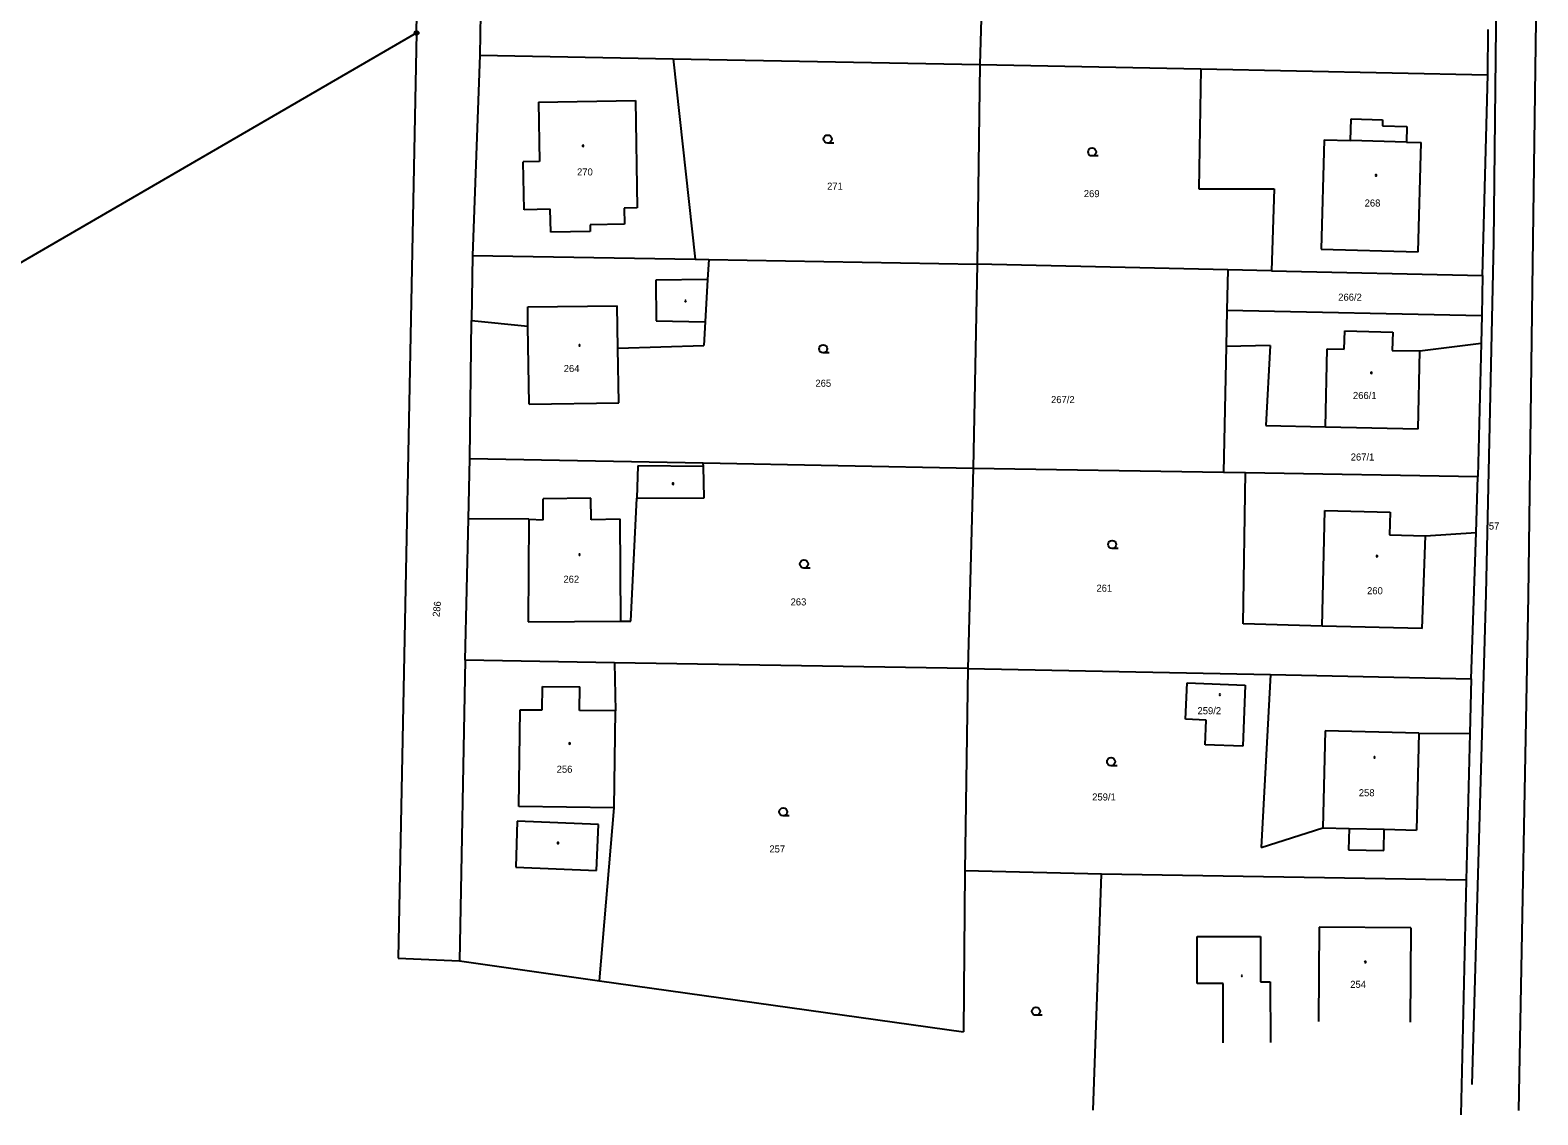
# Model space of a CAD drawing. Extents: x -454285 to -453563, y -1108687 to -1108249.
# Drawn here: x -454018.7 to -453869.2, y -1108668.7 to -1108561.2 of the extents above; entities that cross this region are included whole.
import ezdxf

# ---------------------------------------------------------------- set-up
doc = ezdxf.new("R2010")
doc.units = 0
for name, color, linetype in [('1', 7, 'Continuous'), ('14', 7, 'Continuous'), ('15', 7, 'Continuous'), ('16', 7, 'Continuous'), ('2', 7, 'Continuous'), ('23', 7, 'Continuous'), ('25', 7, 'Continuous'), ('28', 7, 'Continuous')]:
    doc.layers.add(name, color=color, linetype=linetype)

# ---------------------------------------------------------------- blocks, each defined once
blk = doc.blocks.new('Z402')
for start, end in [(0, 180), (180, 0)]:
    blk.add_arc((0, 0), 0.15, start, end)
blk = doc.blocks.new('Z105')
for radius in [0.5, 0.01]:
    blk.add_circle((0, 0), radius)
blk = doc.blocks.new('Z3040')
blk.add_line((1.5, 0), (0, 0))
blk.add_circle((0, 1), 1)

msp = doc.modelspace()

# ---------------------------------------------------------------- linework, layer by layer
at = {"layer": '1'}
for p, q in [((-453980.37, -1108561.48), (-453979.99, -1108542.33)), ((-453923.96, -1108544.79), (-453924.54, -1108564.6)), ((-453974.04, -1108559.6), (-453974.1, -1108563.68)), ((-453874.16, -1108565.63), (-453874.12, -1108561.14)), ((-454149.03, -1108659.33), (-453980.37, -1108561.48)), ((-453980.37, -1108561.48), (-453982.2, -1108653.19)), ((-453974.1, -1108563.68), (-453974.82, -1108583.53)), ((-453974.1, -1108563.68), (-453954.92, -1108564.04)), ((-453954.92, -1108564.04), (-453952.76, -1108583.91)), ((-453954.92, -1108564.04), (-453924.54, -1108564.6)), ((-453924.54, -1108564.6), (-453924.8, -1108584.4)), ((-453924.54, -1108564.6), (-453902.61, -1108565.05)), ((-453902.61, -1108565.05), (-453902.82, -1108576.92)), ((-453902.61, -1108565.05), (-453874.16, -1108565.63)), ((-453874.68, -1108585.52), (-453874.16, -1108565.63)), ((-453902.82, -1108576.92), (-453895.34, -1108576.94)), ((-453895.34, -1108576.94), (-453895.61, -1108585.05)), ((-453974.82, -1108583.53), (-453974.91, -1108589.97)), ((-453974.82, -1108583.53), (-453952.76, -1108583.91)), ((-453952.76, -1108583.91), (-453951.39, -1108583.93)), ((-453951.39, -1108583.93), (-453951.51, -1108585.92)), ((-453951.39, -1108583.93), (-453924.8, -1108584.4)), ((-453924.8, -1108584.4), (-453925.18, -1108604.6)), ((-453908.66, -1108584.76), (-453924.8, -1108584.4)), ((-453899.95, -1108584.95), (-453908.66, -1108584.76)), ((-453899.95, -1108584.95), (-453900.04, -1108588.95)), ((-453895.61, -1108585.05), (-453899.95, -1108584.95)), ((-453895.61, -1108585.05), (-453874.68, -1108585.52)), ((-453951.51, -1108585.92), (-453951.76, -1108590.12)), ((-453874.68, -1108585.52), (-453874.77, -1108589.48)), ((-453900.04, -1108588.95), (-453900.12, -1108592.56)), ((-453900.04, -1108588.95), (-453874.77, -1108589.48)), ((-453874.77, -1108589.48), (-453874.84, -1108592.23)), ((-453975.1, -1108603.67), (-453974.91, -1108589.97)), ((-453974.91, -1108589.97), (-453969.34, -1108590.54)), ((-453969.21, -1108598.27), (-453969.34, -1108590.54)), ((-453951.76, -1108590.12), (-453951.9, -1108592.47)), ((-453960.41, -1108592.74), (-453951.9, -1108592.47)), ((-453895.76, -1108592.46), (-453900.12, -1108592.56)), ((-453895.76, -1108592.46), (-453896.19, -1108600.4)), ((-453880.92, -1108592.98), (-453874.84, -1108592.23)), ((-453874.84, -1108592.23), (-453875.16, -1108605.44)), ((-453960.31, -1108598.15), (-453960.41, -1108592.74)), ((-453900.12, -1108592.56), (-453900.38, -1108605.01)), ((-453881.09, -1108600.73), (-453880.92, -1108592.98)), ((-453969.21, -1108598.27), (-453960.31, -1108598.15)), ((-453896.19, -1108600.4), (-453890.25, -1108600.53)), ((-453890.25, -1108600.53), (-453881.09, -1108600.73)), ((-453975.23, -1108609.64), (-453975.1, -1108603.67)), ((-453975.1, -1108603.67), (-453951.96, -1108604.1)), ((-453951.91, -1108604.44), (-453951.96, -1108604.1)), ((-453951.96, -1108604.1), (-453925.18, -1108604.6)), ((-453951.85, -1108607.56), (-453951.91, -1108604.44)), ((-453925.18, -1108604.6), (-453925.72, -1108624.48)), ((-453925.18, -1108604.6), (-453900.38, -1108605.01)), ((-453900.38, -1108605.01), (-453898.2, -1108605.05)), ((-453898.43, -1108620.05), (-453898.2, -1108605.05)), ((-453898.2, -1108605.05), (-453875.16, -1108605.44)), ((-453875.34, -1108610.99), (-453875.16, -1108605.44)), ((-453959.14, -1108619.77), (-453958.53, -1108607.58)), ((-453958.53, -1108607.58), (-453951.85, -1108607.56)), ((-453975.55, -1108623.65), (-453975.23, -1108609.64)), ((-453969.25, -1108609.68), (-453975.23, -1108609.64)), ((-453969.25, -1108609.68), (-453969.31, -1108619.86)), ((-453880.67, -1108620.52), (-453880.35, -1108611.31)), ((-453880.35, -1108611.31), (-453875.34, -1108610.99)), ((-453875.82, -1108625.48), (-453875.34, -1108610.99)), ((-453969.31, -1108619.86), (-453960.11, -1108619.78)), ((-453960.11, -1108619.78), (-453959.14, -1108619.77)), ((-453890.59, -1108620.29), (-453898.43, -1108620.05)), ((-453880.67, -1108620.52), (-453890.59, -1108620.29)), ((-453975.55, -1108623.65), (-453976.12, -1108653.45)), ((-453960.74, -1108623.9), (-453975.55, -1108623.65)), ((-453960.74, -1108623.9), (-453960.66, -1108628.67)), ((-453925.72, -1108624.48), (-453960.74, -1108623.9)), ((-453925.72, -1108624.48), (-453926.02, -1108644.53)), ((-453925.72, -1108624.48), (-453895.7, -1108625.08)), ((-453895.7, -1108625.08), (-453896.63, -1108642.22)), ((-453895.7, -1108625.08), (-453875.82, -1108625.48)), ((-453904.14, -1108629.5), (-453903.98, -1108625.88)), ((-453903.98, -1108625.88), (-453898.23, -1108626.12)), ((-453898.23, -1108626.12), (-453898.47, -1108632.16)), ((-453875.82, -1108625.48), (-453875.96, -1108630.91)), ((-453960.77, -1108638.27), (-453960.66, -1108628.67)), ((-453902.09, -1108629.59), (-453904.14, -1108629.5)), ((-453902.19, -1108632.04), (-453902.09, -1108629.59)), ((-453881.01, -1108630.87), (-453881.25, -1108640.49)), ((-453881.01, -1108630.87), (-453875.96, -1108630.91)), ((-453875.96, -1108630.91), (-453876.32, -1108645.44)), ((-453898.47, -1108632.16), (-453902.19, -1108632.04)), ((-453962.22, -1108655.41), (-453960.77, -1108638.27)), ((-453896.63, -1108642.22), (-453890.51, -1108640.27)), ((-453890.51, -1108640.27), (-453887.92, -1108640.33)), ((-453887.92, -1108640.33), (-453887.98, -1108642.43)), ((-453884.49, -1108642.51), (-453884.44, -1108640.4)), ((-453884.44, -1108640.4), (-453881.25, -1108640.49)), ((-453887.98, -1108642.43), (-453884.49, -1108642.51)), ((-453926.02, -1108644.53), (-453926.16, -1108660.49)), ((-453912.48, -1108644.85), (-453926.02, -1108644.53)), ((-453913.28, -1108668.23), (-453912.48, -1108644.85)), ((-453876.32, -1108645.44), (-453912.48, -1108644.85)), ((-453876.32, -1108645.44), (-453876.83, -1108668.7)), ((-453982.2, -1108653.19), (-453976.12, -1108653.45)), ((-453976.12, -1108653.45), (-453962.22, -1108655.41)), ((-453962.22, -1108655.41), (-453926.16, -1108660.49))]:
    msp.add_line(p, q, dxfattribs=at)
at = {"layer": '2'}
for p, q in [((-453873.17, -1108541.89), (-453873.61, -1108582.22)), ((-453869.73, -1108586.75), (-453869.15, -1108543.86)), ((-453968.28, -1108568.34), (-453958.68, -1108568.18)), ((-453968.28, -1108568.34), (-453968.18, -1108574.24)), ((-453958.68, -1108568.18), (-453958.5, -1108578.82)), ((-453887.79, -1108572.16), (-453887.73, -1108570)), ((-453887.73, -1108570), (-453884.6, -1108570.09)), ((-453884.6, -1108570.09), (-453884.62, -1108570.69)), ((-453884.62, -1108570.69), (-453882.19, -1108570.76)), ((-453882.19, -1108570.76), (-453882.23, -1108572.3)), ((-453890.38, -1108572.09), (-453890.68, -1108582.91)), ((-453890.38, -1108572.09), (-453887.79, -1108572.16)), ((-453882.23, -1108572.3), (-453887.79, -1108572.16)), ((-453882.23, -1108572.3), (-453880.78, -1108572.35)), ((-453881.08, -1108583.17), (-453880.78, -1108572.35)), ((-453968.18, -1108574.24), (-453969.81, -1108574.27)), ((-453969.69, -1108579), (-453969.81, -1108574.27)), ((-453967.11, -1108578.96), (-453969.69, -1108579)), ((-453967.07, -1108581.22), (-453967.11, -1108578.96)), ((-453958.5, -1108578.82), (-453959.78, -1108578.84)), ((-453959.78, -1108578.84), (-453959.75, -1108580.44)), ((-453959.75, -1108580.44), (-453963.17, -1108580.5)), ((-453963.17, -1108580.5), (-453963.16, -1108581.15)), ((-453963.16, -1108581.15), (-453967.07, -1108581.22)), ((-453890.68, -1108582.91), (-453881.08, -1108583.17)), ((-453873.61, -1108582.22), (-453874.38, -1108617.06)), ((-453951.51, -1108585.92), (-453956.64, -1108586)), ((-453956.64, -1108586), (-453956.6, -1108590)), ((-453870.13, -1108617.26), (-453869.73, -1108586.75)), ((-453969.34, -1108588.64), (-453960.49, -1108588.52)), ((-453969.34, -1108590.54), (-453969.34, -1108588.64)), ((-453960.41, -1108592.74), (-453960.49, -1108588.52)), ((-453956.6, -1108590), (-453951.76, -1108590.12)), ((-453888.4, -1108592.82), (-453888.36, -1108591.02)), ((-453888.36, -1108591.02), (-453883.6, -1108591.13)), ((-453883.6, -1108591.13), (-453883.64, -1108592.95)), ((-453890.25, -1108600.53), (-453890.08, -1108592.78)), ((-453890.08, -1108592.78), (-453888.4, -1108592.82)), ((-453883.64, -1108592.95), (-453880.92, -1108592.98)), ((-453958.44, -1108604.38), (-453958.53, -1108607.58)), ((-453951.91, -1108604.44), (-453958.44, -1108604.38)), ((-453963.08, -1108607.6), (-453967.83, -1108607.65)), ((-453967.81, -1108609.75), (-453967.83, -1108607.65)), ((-453963.06, -1108609.72), (-453963.08, -1108607.6)), ((-453890.59, -1108620.29), (-453890.32, -1108608.82)), ((-453890.32, -1108608.82), (-453883.86, -1108608.97)), ((-453883.86, -1108608.97), (-453883.91, -1108611.23)), ((-453969.25, -1108609.68), (-453967.81, -1108609.75)), ((-453960.2, -1108609.68), (-453963.06, -1108609.72)), ((-453960.11, -1108619.78), (-453960.2, -1108609.68)), ((-453883.91, -1108611.23), (-453880.35, -1108611.31)), ((-453874.38, -1108617.06), (-453875.74, -1108665.68)), ((-453871.08, -1108668.28), (-453870.13, -1108617.26)), ((-453967.91, -1108628.58), (-453967.88, -1108626.24)), ((-453967.88, -1108626.24), (-453964.18, -1108626.28)), ((-453964.21, -1108628.63), (-453964.18, -1108626.28)), ((-453970.22, -1108638.16), (-453970.11, -1108628.56)), ((-453970.11, -1108628.56), (-453967.91, -1108628.58)), ((-453960.66, -1108628.67), (-453964.21, -1108628.63)), ((-453890.28, -1108630.65), (-453890.51, -1108640.27)), ((-453881.01, -1108630.87), (-453890.28, -1108630.65)), ((-453960.77, -1108638.27), (-453970.22, -1108638.16)), ((-453970.4, -1108639.6), (-453970.52, -1108644.16)), ((-453962.32, -1108639.93), (-453970.4, -1108639.6)), ((-453962.52, -1108644.49), (-453962.32, -1108639.93)), ((-453887.92, -1108640.33), (-453884.44, -1108640.4)), ((-453970.52, -1108644.16), (-453962.52, -1108644.49)), ((-453890.88, -1108650.1), (-453890.96, -1108659.45)), ((-453881.8, -1108650.18), (-453890.88, -1108650.1)), ((-453881.8, -1108650.18), (-453881.88, -1108659.53)), ((-453902.98, -1108651.04), (-453896.72, -1108651.03)), ((-453902.97, -1108655.68), (-453902.98, -1108651.04)), ((-453896.72, -1108651.03), (-453896.71, -1108655.52)), ((-453900.42, -1108655.68), (-453902.97, -1108655.68)), ((-453900.41, -1108661.55), (-453900.42, -1108655.68)), ((-453896.71, -1108655.52), (-453895.73, -1108655.52)), ((-453895.73, -1108655.52), (-453895.72, -1108661.54))]:
    msp.add_line(p, q, dxfattribs=at)

# ---------------------------------------------------------------- block references
at = {"layer": '23', "xscale": 0.4, "yscale": 0.4000000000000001}
for p in [(-453939.61, -1108572.4), (-453913.4, -1108573.68), (-453940.06, -1108593.19), (-453911.41, -1108612.57), (-453941.96, -1108614.51), (-453911.52, -1108634.1), (-453944.02, -1108639.08), (-453918.96, -1108658.84)]:
    msp.add_blockref('Z3040', p, dxfattribs=at)
at = {"layer": '25', "xscale": 0.4, "yscale": 0.4000000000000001}
for p in [(-453963.87, -1108572.68), (-453885.26, -1108575.6), (-453953.7, -1108588.05), (-453964.22, -1108592.44), (-453885.72, -1108595.17), (-453954.95, -1108606.16), (-453964.22, -1108613.19), (-453885.15, -1108613.33), (-453900.74, -1108627.06), (-453965.19, -1108631.9), (-453885.4, -1108633.27), (-453966.35, -1108641.76), (-453886.32, -1108653.56), (-453898.56, -1108654.92)]:
    msp.add_blockref('Z402', p, dxfattribs=at)
at = {"layer": '28', "xscale": 0.4, "yscale": 0.4000000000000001}
msp.add_blockref('Z105', (-453980.37, -1108561.48), dxfattribs=at)

# ---------------------------------------------------------------- texts
at = {"layer": '14'}
for s, p in [('271', (-453939.67, -1108577.02)), ('269', (-453914.22, -1108577.76)), ('266/2', (-453889, -1108588.02)), ('265', (-453940.83, -1108596.55)), ('267/2', (-453917.47, -1108598.17)), ('267/1', (-453887.76, -1108603.86)), ('261', (-453912.97, -1108616.86)), ('263', (-453943.29, -1108618.22)), ('259/1', (-453913.39, -1108637.55)), ('257', (-453945.39, -1108642.7))]:
    msp.add_text(s, height=0.7, dxfattribs=at).set_placement(p)
at = {"layer": '15'}
for s, p in [('270', (-453964.46, -1108575.61)), ('268', (-453886.38, -1108578.69)), ('264', (-453965.78, -1108595.09)), ('266/1', (-453887.54, -1108597.76)), ('262', (-453965.81, -1108615.97)), ('260', (-453886.14, -1108617.11)), ('259/2', (-453902.95, -1108629)), ('256', (-453966.48, -1108634.8)), ('258', (-453886.96, -1108637.13)), ('254', (-453887.81, -1108656.12))]:
    msp.add_text(s, height=0.7, dxfattribs=at).set_placement(p)
at = {"layer": '16'}
msp.add_text('57', height=0.7, dxfattribs=at).set_placement((-453874.07, -1108610.7))
msp.add_text('286', height=0.7, rotation=84.114, dxfattribs=at).set_placement((-453978.09, -1108619.39))

doc.saveas('drawing.dxf')
